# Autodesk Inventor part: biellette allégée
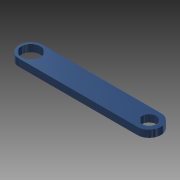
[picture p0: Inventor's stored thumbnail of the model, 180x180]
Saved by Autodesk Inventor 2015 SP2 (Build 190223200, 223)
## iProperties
Created: 2015-08
Part Number: biellette allégée
Material: Générique
Document SubType Name: Modeling
Designer: Dominique
Density: 1 g/cm^3
Appearance: Satiné en paillette - Bleu
Author: Dominique
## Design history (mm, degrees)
sketch "Esquisse1"
  geometry: L1 (60, 5)-(60, 5); L2 (0, 5)-(0, 5); L3 (5, 0)-(8.108, 0); L4 (8.108, 0)-(55, 0); L5 (55, 10)-(8.108, 10); L6 (8.108, 10)-(5, 10); C1 r 4 at (5, 5); C2 r 3 at (55, 5); A1 r 5 centre (5, 5) between (5, 10) and (0, 5); A2 r 5 centre (5, 5) between (0, 5) and (5, 0); A3 r 5 centre (55, 5) between (60, 5) and (55, 10); A4 r 5 centre (55, 5) between (55, 0) and (60, 5); 9 further points
  constraints: 12 end point, 12 tangent, 9 point on line, 8 point on circle, 6 centre point, 5 parallel, 3 equal radius, 2 coincident, 2 horizontal, 2 perpendicular
  dimensions: "d0" = 60 distance of point (0, 10) point (60, 10); "d2" = 5 radius of A1; "d3" = 8 diameter of C1; "d4" = 6 diameter of C2; "d8" = 5 radius of A3 (derived)
extrude "Extrusion1" new body sketch "Esquisse1" distance "d6" = 3; taper "d7" = 0 deg
node "Solide1"
